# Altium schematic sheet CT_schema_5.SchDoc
size 322 x 309 mm
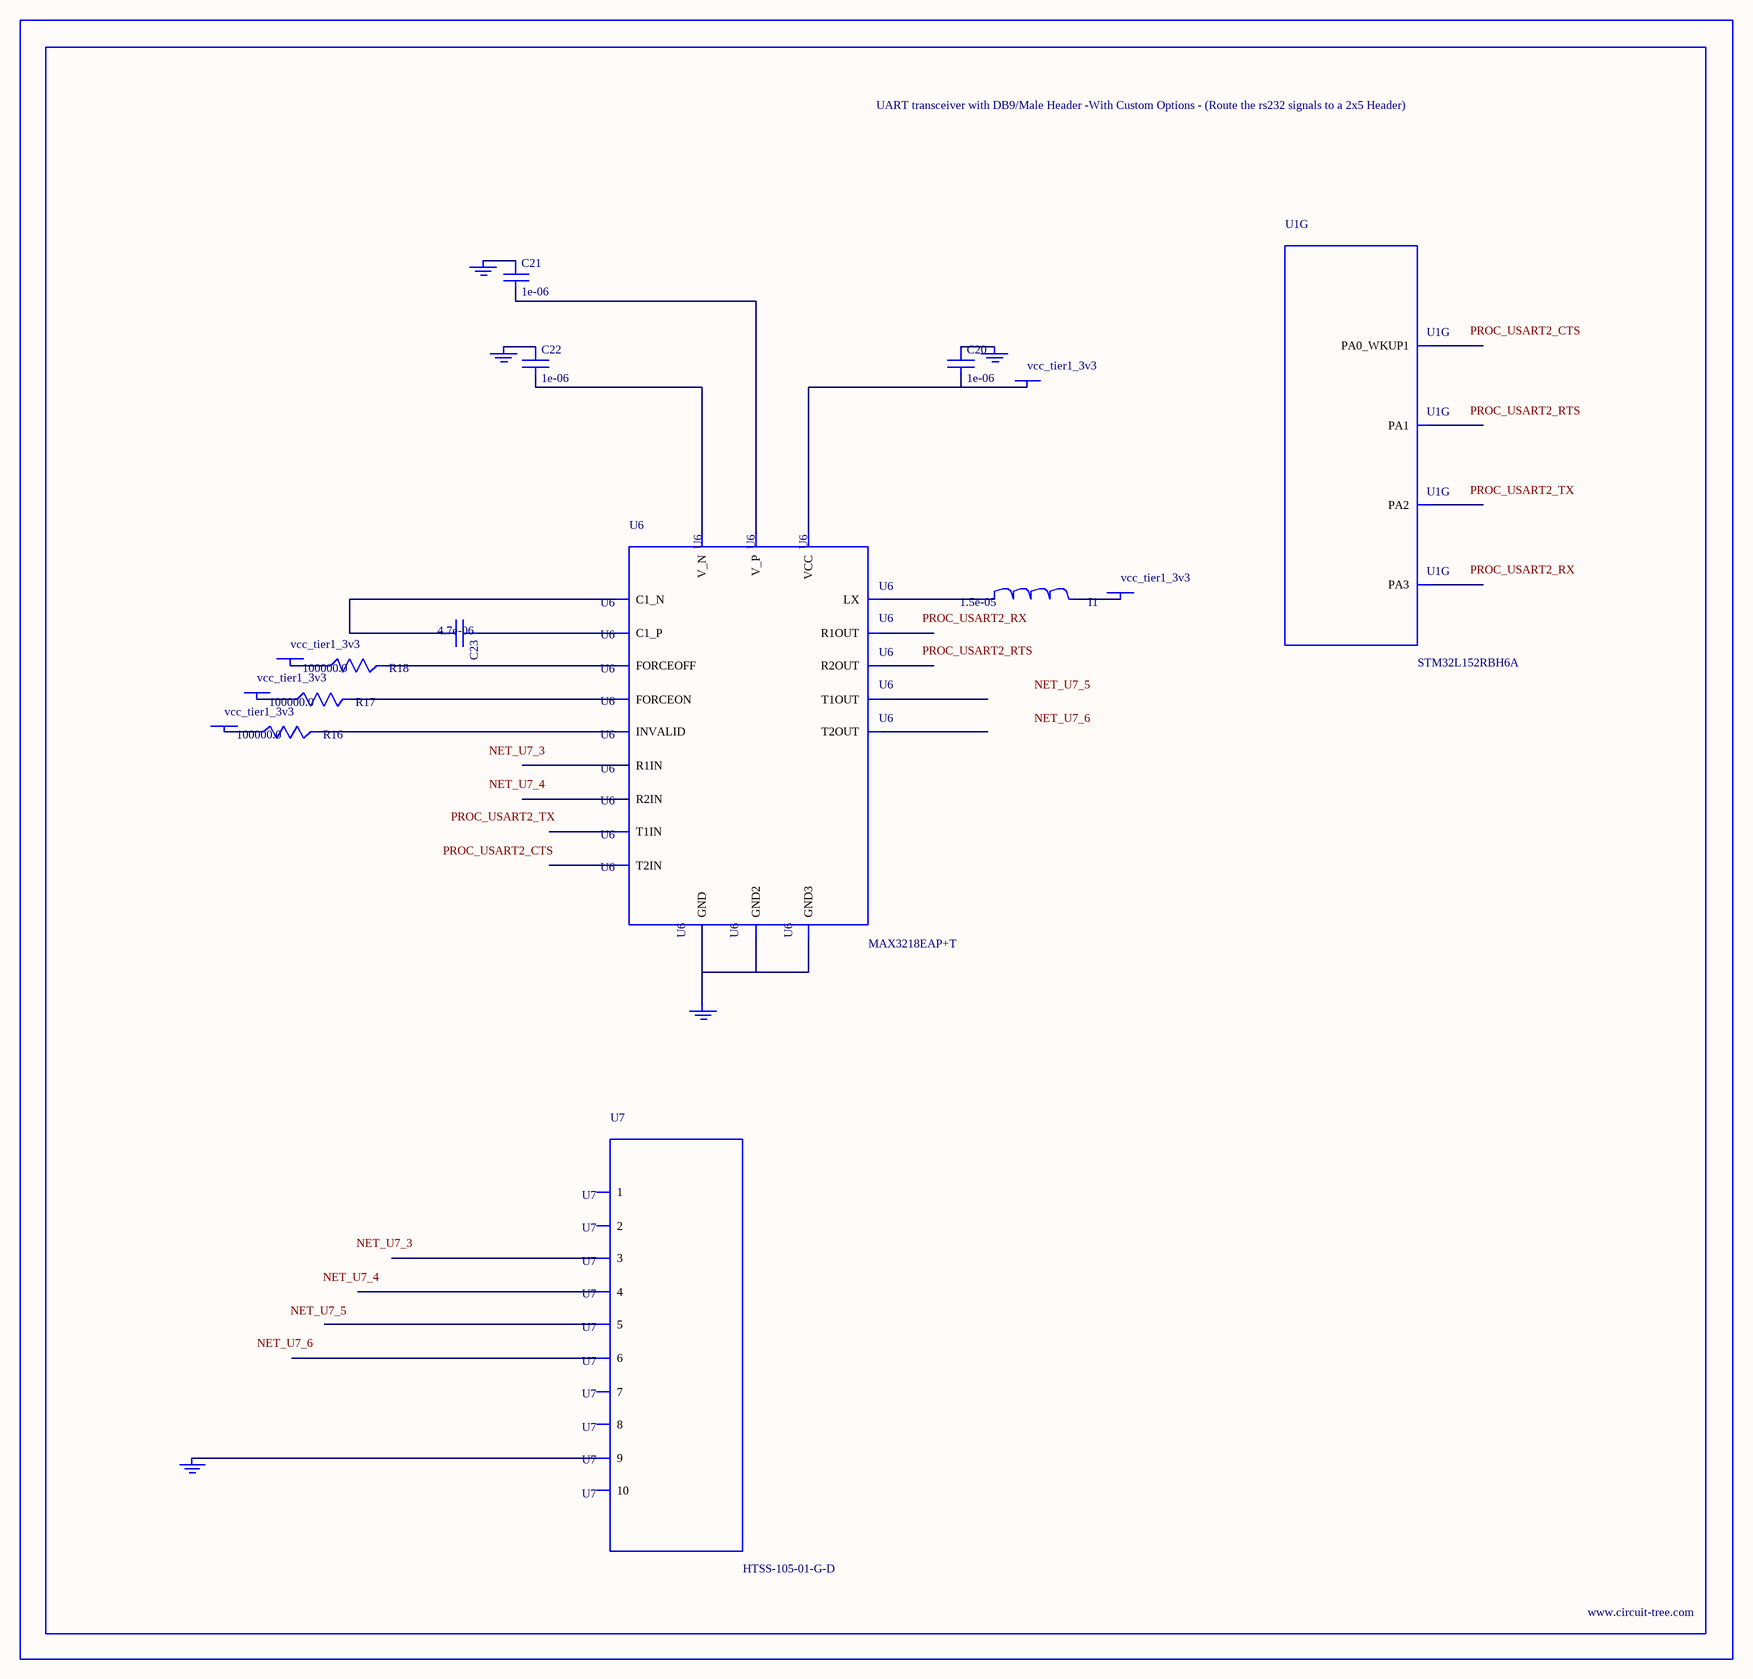
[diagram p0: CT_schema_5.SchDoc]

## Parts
BORDER4  (no value)
C20  1e-06  [C0603]
C21  1e-06  [C0603]
C22  1e-06  [C0603]
C23  4.7e-06  [C0805]
GND_INSTANCE_4_0  (no value)
GND_INSTANCE_4_1  (no value)
GND_INSTANCE_4_2  (no value)
GND_INSTANCE_4_3  (no value)
GND_INSTANCE_4_4  (no value)
I1  1.5e-05  [L1210]
POWER_INSTANCE_4_0  vcc_tier1_3v3
POWER_INSTANCE_4_1  vcc_tier1_3v3
POWER_INSTANCE_4_2  vcc_tier1_3v3
POWER_INSTANCE_4_3  vcc_tier1_3v3
POWER_INSTANCE_4_4  vcc_tier1_3v3
R16  100000.0  [R0603]
R17  100000.0  [R0603]
R18  100000.0  [R0603]
U1  STM32L152RBH6A  [TFBGA64]  (part G of 7)
U6  MAX3218EAP+T  [SSOP-20]
U7  HTSS-105-01-G-D  [HTSS-105-01-G-D]

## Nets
NetC20_1: C20.1 GND_INSTANCE_4_0.0(GND)
NetC20_2: C20.2 POWER_INSTANCE_4_4.0(PWR) U6.6(VCC)
NetC21_1: C21.1 GND_INSTANCE_4_2.0(GND)
NetC21_2: C21.2 U6.19(V_P)
NetC22_1: C22.1 GND_INSTANCE_4_1.0(GND)
NetC22_2: C22.2 U6.15(V_N)
NetC23_1: C23.1 U6.18(C1_P)
NetC23_2: C23.2 U6.16(C1_N)
NetGND_INSTANCE_4_3_0: GND_INSTANCE_4_3.0(GND) U6.5(GND) U6.17(GND2) U6.20(GND3)
NetGND_INSTANCE_4_4_0: GND_INSTANCE_4_4.0(GND) U7.9
NetI1_1: I1.1 U6.1(LX)
NetI1_2: I1.2 POWER_INSTANCE_4_0.0(PWR)
NetPOWER_INSTANCE_4_1_0: POWER_INSTANCE_4_1.0(PWR) R16.1
NetPOWER_INSTANCE_4_2_0: POWER_INSTANCE_4_2.0(PWR) R17.1
NetPOWER_INSTANCE_4_3_0: POWER_INSTANCE_4_3.0(PWR) R18.1
NetR16_2: R16.2 U6.2(INVALID)
NetR17_2: R17.2 U6.3(FORCEON)
NetR18_2: R18.2 U6.4(FORCEOFF)

Not connected (* = marked no-connect by the designer): U1 F3(PA2) G2(PA0_WKUP1) G3(PA3) H2(PA1); U6 7(T1IN) 8(T2IN) 9(R1OUT) 10(R2OUT) 11(R2IN) 12(R1IN) 13(T2OUT) 14(T1OUT); U7 1 2 3 4 5 6 7 8 10

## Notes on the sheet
- Labels drawn without touching a wire or pin: NET_U7_3, NET_U7_4, NET_U7_5, NET_U7_6, PROC_USART2_CTS, PROC_USART2_RTS, PROC_USART2_RX, PROC_USART2_TX

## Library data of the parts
BORDER4 = BORDER_PAGE4
C20-C22 = C0603C105K3RACTU
C23 = C0805C475K4RACTU
GND_INSTANCE_4_0-GND_INSTANCE_4_4 = GND
I1 = L1210R150MDWIT
POWER_INSTANCE_4_0-POWER_INSTANCE_4_4 = PWR
R16-R18 = RC0603JR-07100KL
